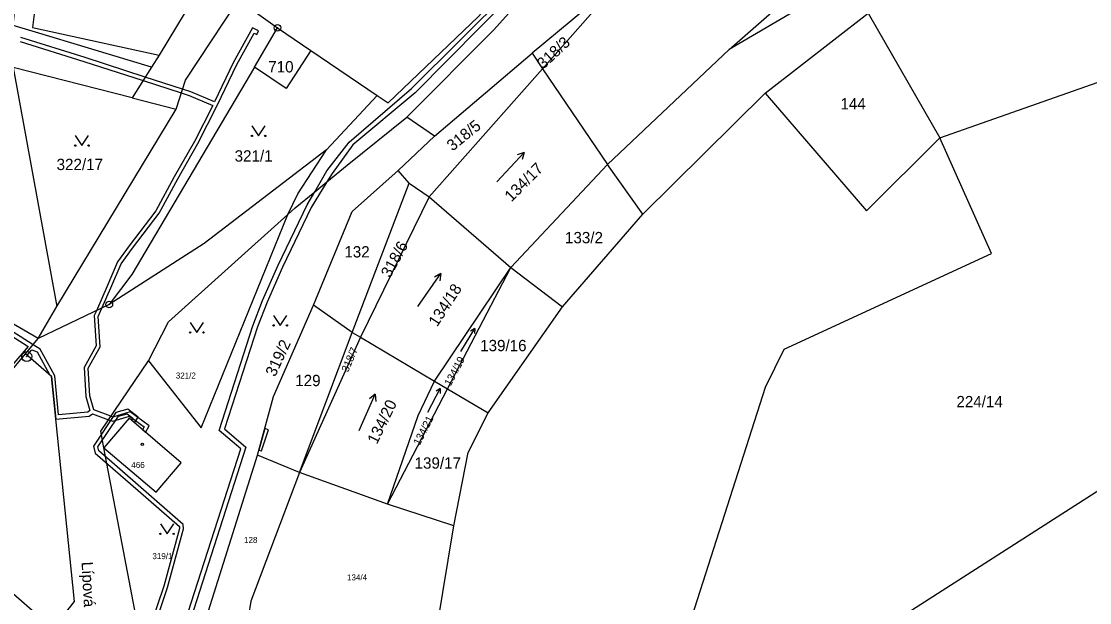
# Model space of a CAD drawing. Extents: x -758582 to -751794, y -998770 to -994350.
# Drawn here: x -755587.2 to -755427.1, y -995334.3 to -995247.1 of the extents above; entities that cross this region are included whole.
import ezdxf

# ---------------------------------------------------------------- set-up
doc = ezdxf.new("R2010")
doc.units = 0
for name, color, linetype in [('Hranice parcel', 7, 'Continuous'), ('Parcelní čísla', 7, 'Continuous'), ('Pop  PČ popisy', 7, 'Continuous'), ('Věcná břemena k části', 7, 'Continuous'), ('Značky bodu BP', 7, 'Continuous'), ('Značky budov', 7, 'Continuous'), ('Značky kultur', 7, 'Continuous')]:
    doc.layers.add(name, color=color, linetype=linetype)

msp = doc.modelspace()

# ---------------------------------------------------------------- linework, layer by layer
at = {"layer": 'Hranice parcel'}
for p, q in [((-755554.28, -995231.7), (-755566.56, -995252.17)), ((-755497.8, -995241.41), (-755509.1, -995254.2)), ((-755475.72, -995257.89), (-755460.26, -995245.87)), ((-755460.26, -995245.87), (-755449.56, -995264.56)), ((-755567.7, -995253.96), (-755585.62, -995248.58)), ((-755552.29, -995253.96), (-755548.82, -995248.07)), ((-755548.82, -995248.07), (-755543.84, -995251.46)), ((-755543.84, -995251.46), (-755533.88, -995258.24)), ((-755525.3, -995264.33), (-755510.67, -995251.89)), ((-755510.67, -995251.89), (-755509.1, -995254.2)), ((-755499.35, -995268.57), (-755481.13, -995251.3)), ((-755566.56, -995252.17), (-755567.7, -995253.96)), ((-755567.7, -995253.96), (-755570.64, -995258.57)), ((-755509.1, -995254.2), (-755526.08, -995273.42)), ((-755509.1, -995254.2), (-755499.35, -995268.57)), ((-755533.88, -995258.24), (-755541.47, -995266.38)), ((-755494.08, -995276.04), (-755475.72, -995257.89)), ((-755570.64, -995258.57), (-755564.04, -995260.28)), ((-755581.92, -995289.89), (-755564.04, -995260.28)), ((-755525.3, -995264.33), (-755529.42, -995261.45)), ((-755530.73, -995269.49), (-755525.3, -995264.33)), ((-755541.42, -995269.53), (-755538.1, -995265.23)), ((-755537.53, -995265.64), (-755540.66, -995269.92)), ((-755543.25, -995272.66), (-755541.42, -995269.53)), ((-755529.08, -995271.36), (-755530.73, -995269.49)), ((-755499.35, -995268.57), (-755513.85, -995284.01)), ((-755494.08, -995276.04), (-755499.35, -995268.57)), ((-755541.43, -995271.17), (-755543.8, -995275.01)), ((-755543.25, -995272.66), (-755541.43, -995271.17)), ((-755540.66, -995269.92), (-755541.43, -995271.17)), ((-755544.39, -995274.61), (-755543.25, -995272.66)), ((-755537.63, -995293.77), (-755529.08, -995271.36)), ((-755529.08, -995271.36), (-755526.08, -995273.42)), ((-755526.08, -995273.42), (-755536.41, -995294.48)), ((-755526.08, -995273.42), (-755513.85, -995284.01)), ((-755506.1, -995289.9), (-755494.08, -995276.04)), ((-755525.31, -995301.08), (-755513.85, -995284.01)), ((-755523.35, -995302.23), (-755513.85, -995284.01)), ((-755513.85, -995284.01), (-755506.1, -995289.9)), ((-755574.05, -995289.57), (-755584.69, -995294.66)), ((-755584.69, -995294.66), (-755581.92, -995289.89)), ((-755537.63, -995293.77), (-755543.42, -995289.65)), ((-755517.23, -995305.83), (-755506.1, -995289.9)), ((-755586.61, -995296.97), (-755584.69, -995294.66)), ((-755545.52, -995314.78), (-755537.63, -995293.77)), ((-755536.41, -995294.48), (-755545.52, -995314.78)), ((-755537.63, -995293.77), (-755536.41, -995294.48)), ((-755536.41, -995294.48), (-755525.31, -995301.08)), ((-755525.31, -995301.08), (-755523.35, -995302.23)), ((-755532.36, -995319.53), (-755523.35, -995302.23)), ((-755523.35, -995302.23), (-755517.23, -995305.83)), ((-755559.19, -995335.53), (-755551.84, -995312.15)), ((-755545.52, -995314.78), (-755551.84, -995312.15)), ((-755532.36, -995319.53), (-755545.52, -995314.78)), ((-755582.49, -995338.18), (-755604.83, -995318.78)), ((-755522.4, -995322.78), (-755532.36, -995319.53)), ((-755525.07, -995339.05), (-755522.4, -995322.78))]:
    msp.add_line(p, q, dxfattribs=at)
for points in [[(-755538.1, -995265.23), (-755528.73, -995257.18), (-755514.16, -995242.6), (-755505.01, -995231.64), (-755487.77, -995216.43), (-755485.53, -995215.06), (-755445.75, -995194.77), (-755445.41, -995195.37), (-755485.15, -995215.66), (-755487.28, -995216.99), (-755504.51, -995232.13), (-755513.52, -995242.92), (-755528.17, -995257.81), (-755537.53, -995265.64)], [(-755529.42, -995261.45), (-755516.42, -995248.35), (-755493.01, -995222.25), (-755447.53, -995198.48)], [(-755481.13, -995251.3), (-755457.2, -995230.32), (-755418.43, -995216.03), (-755380.2, -995211.02), (-755336.91, -995218.43)], [(-755534.63, -995218.44), (-755552.33, -995245.58), (-755548.82, -995248.07)], [(-755386.67, -995226.04), (-755412.78, -995223.97), (-755437.13, -995226.79), (-755445.78, -995230.58), (-755481.13, -995251.3)], [(-755585.62, -995248.58), (-755588.45, -995247.73), (-755586.35, -995227.86)], [(-755564.04, -995260.28), (-755562.65, -995255.93), (-755543.32, -995226.65)], [(-755533.88, -995258.24), (-755532.26, -995259.34), (-755518.72, -995246.36), (-755506.35, -995232.39)], [(-755497.8, -995241.41), (-755502.77, -995245.31), (-755510.67, -995251.89)], [(-755585.26, -995245.62), (-755585.57, -995248), (-755566.56, -995252.17)], [(-755543.84, -995251.46), (-755547.55, -995257.18), (-755552.29, -995253.96)], [(-755570.64, -995258.57), (-755588.47, -995254.04), (-755581.92, -995289.89)], [(-755552.29, -995253.96), (-755570.65, -995285.06), (-755574.05, -995289.57)], [(-755449.56, -995264.56), (-755424.12, -995255.64), (-755410.64, -995253.98)], [(-755475.72, -995257.89), (-755472.3, -995261.82), (-755460.52, -995275.52), (-755449.56, -995264.56)], [(-755541.43, -995271.17), (-755538.37, -995268.67), (-755529.42, -995261.45)], [(-755584.69, -995294.66), (-755603.13, -995283.98), (-755600.61, -995263.4)], [(-755401.75, -995302.11), (-755494.82, -995361.79), (-755475.68, -995301.95), (-755472.86, -995296.26), (-755441.79, -995281.92), (-755449.56, -995264.56)], [(-755541.47, -995266.38), (-755559.84, -995280.42), (-755574.05, -995289.57)], [(-755547.3, -995276.08), (-755545.81, -995272.96), (-755541.47, -995266.38)], [(-755543.42, -995289.65), (-755537.66, -995275.61), (-755530.73, -995269.49)], [(-755547.3, -995276.08), (-755546.19, -995275.06), (-755543.25, -995272.66)], [(-755564.23, -995341.93), (-755554.34, -995311.23), (-755557.56, -995308.48), (-755552.53, -995292.76), (-755551.06, -995288.97), (-755548.71, -995283.66), (-755544.39, -995274.61)], [(-755543.8, -995275.01), (-755548.06, -995283.95), (-755550.36, -995289.2), (-755551.83, -995292.94), (-755556.78, -995308.24), (-755553.56, -995310.96), (-755563.56, -995342.14)], [(-755568.18, -995298.04), (-755560.3, -995308.05), (-755547.3, -995276.08)], [(-755568.18, -995298.04), (-755565.17, -995292.15), (-755547.3, -995276.08)], [(-755551.84, -995312.15), (-755549.43, -995303.35), (-755543.42, -995289.65)], [(-755604.83, -995318.78), (-755602.92, -995316.56), (-755586.61, -995296.97)], [(-755582.49, -995338.18), (-755579.25, -995334.13), (-755582.7, -995300.36), (-755586.61, -995296.97)], [(-755566.67, -995354.01), (-755574.85, -995311.05), (-755575.32, -995308.58), (-755568.18, -995298.04)], [(-755532.36, -995319.53), (-755527.75, -995306.22), (-755525.31, -995301.08)], [(-755522.4, -995322.78), (-755520.25, -995311.79), (-755517.23, -995305.83)], [(-755563.27, -995313.31), (-755571.09, -995306.64), (-755574.85, -995311.05), (-755567.03, -995317.72), (-755563.27, -995313.31)], [(-755545.52, -995314.78), (-755552.84, -995334.08), (-755553.18, -995336.27)]]:
    msp.add_lwpolyline(points, dxfattribs=at)
at = {"layer": 'Věcná břemena k části'}
for points in [[(-755551.93, -995249.05), (-755551.66, -995248.51), (-755552.58, -995248.05), (-755555.49, -995253.3), (-755558.28, -995259.19), (-755561.85, -995257.65), (-755563.07, -995257.26), (-755568.65, -995255.45), (-755577.66, -995252.53), (-755587.33, -995249.51)], [(-755598.06, -995310.72), (-755586.61, -995296.97), (-755586.35, -995297.19), (-755585.64, -995296.39), (-755584.88, -995296.68), (-755583.03, -995300.07), (-755582.7, -995300.36), (-755582.05, -995306.77), (-755577.08, -995306.33), (-755576.55, -995305.95), (-755574.15, -995306.85), (-755573.52, -995307.09), (-755571.01, -995306.33), (-755568.83, -995307.92), (-755569.08, -995308.35), (-755568.62, -995308.75), (-755568.05, -995307.76), (-755570.9, -995305.67), (-755573.5, -995306.45), (-755573.8, -995306.34), (-755576.35, -995305.38), (-755576.98, -995303.25), (-755577.22, -995299.14), (-755575.42, -995295.93), (-755575.71, -995291.35), (-755575.15, -995290.1), (-755573.8, -995287.07), (-755572.28, -995283.49), (-755570.57, -995281.11), (-755566.55, -995275.86), (-755563.8, -995270.71), (-755560.77, -995265.4), (-755557.87, -995259.72), (-755554.95, -995253.58), (-755552.33, -995248.85), (-755551.93, -995249.05)], [(-755587.43, -995250.11), (-755577.85, -995253.1), (-755568.98, -995255.97), (-755563.26, -995257.83), (-755562.06, -995258.22), (-755558.55, -995259.73), (-755561.3, -995265.11), (-755564.33, -995270.42), (-755567.05, -995275.53), (-755571.05, -995280.75), (-755572.8, -995283.19), (-755574.35, -995286.83), (-755575.99, -995290.5), (-755576.32, -995291.24), (-755576.03, -995295.79), (-755577.83, -995299), (-755577.57, -995303.35), (-755576.95, -995305.49), (-755577.29, -995305.74), (-755581.69, -995306.13), (-755582.23, -995300.29), (-755584.41, -995296.29), (-755585.48, -995295.61), (-755592.48, -995291.16)], [(-755643.48, -995337.62), (-755640.25, -995330.48), (-755639.7, -995328.7), (-755632.03, -995328.47), (-755628.34, -995328.42), (-755627.31, -995328.4), (-755621.32, -995321.76), (-755620.58, -995321.49), (-755617.34, -995317.71), (-755616.99, -995316.75), (-755615.43, -995314.83), (-755604.67, -995302.41), (-755603.71, -995289), (-755596.35, -995289.57), (-755592.79, -995291.68), (-755586.22, -995295.85), (-755593.89, -995304.76), (-755600.06, -995312.07), (-755604.15, -995316.69), (-755606.29, -995318.13), (-755608.5, -995320.68), (-755608.78, -995321.82), (-755616.14, -995330.47), (-755621.57, -995336.43)], [(-755569.29, -995343.8), (-755565.32, -995332.01), (-755562.91, -995323.22), (-755562.96, -995322.56), (-755569.31, -995317.02), (-755575.61, -995311.53), (-755575.76, -995310.92), (-755572.67, -995306.31), (-755571.39, -995305.95), (-755570.52, -995306.62), (-755570.73, -995306.92), (-755570.74, -995306.94), (-755570.27, -995307.32), (-755569.7, -995306.49), (-755571.26, -995305.29), (-755573.05, -995305.79), (-755576.41, -995310.8), (-755576.15, -995311.86), (-755569.7, -995317.47), (-755563.54, -995322.85), (-755563.52, -995323.17), (-755565.89, -995331.83), (-755569.86, -995343.61)]]:
    msp.add_lwpolyline(points, dxfattribs=at)
msp.add_lwpolyline([(-755551.64, -995311.41), (-755551.23, -995311.54), (-755550.17, -995308.38), (-755550.75, -995308.18)], close=True, dxfattribs=at)
at = {"layer": 'Značky bodu BP'}
for centre, radius in [((-755548.82, -995248.07), 0.5), ((-755548.82, -995248.07), 0.0303), ((-755574.05, -995289.57), 0.5), ((-755574.05, -995289.57), 0.0303), ((-755586.43, -995297.38), 0.75), ((-755586.43, -995297.38), 0.03)]:
    msp.add_circle(centre, radius, dxfattribs=at)
at = {"layer": 'Značky budov'}
msp.add_circle((-755569.1, -995310.55), 0.175, dxfattribs=at)
at = {"layer": 'Značky kultur'}
for p, q in [((-755515.96, -995271.15), (-755511.87, -995266.76)), ((-755511.87, -995266.76), (-755512.9, -995267.13)), ((-755511.87, -995266.76), (-755512.17, -995267.82)), ((-755527.77, -995289.86), (-755524.33, -995284.94)), ((-755524.33, -995284.94), (-755525.3, -995285.46)), ((-755524.33, -995284.94), (-755524.48, -995286.03)), ((-755521.37, -995296.6), (-755519.24, -995293.19)), ((-755519.24, -995293.19), (-755519.88, -995293.57)), ((-755519.24, -995293.19), (-755519.31, -995293.92)), ((-755536.6, -995308.49), (-755534.17, -995303.01)), ((-755534.17, -995303.01), (-755535.02, -995303.7)), ((-755534.17, -995303.01), (-755534.1, -995304.1)), ((-755526.32, -995305.72), (-755524.44, -995302.17)), ((-755524.44, -995302.17), (-755525.04, -995302.59)), ((-755524.44, -995302.17), (-755524.45, -995302.9))]:
    msp.add_line(p, q, dxfattribs=at)
for points in [[(-755552.67, -995262.79), (-755551.67, -995264.29), (-755550.67, -995262.79)], [(-755579.16, -995264.24), (-755578.16, -995265.74), (-755577.16, -995264.24)], [(-755549.42, -995291.21), (-755548.42, -995292.71), (-755547.42, -995291.21)], [(-755561.93, -995292.25), (-755560.93, -995293.75), (-755559.93, -995292.25)], [(-755566.39, -995322.47), (-755565.39, -995323.97), (-755564.39, -995322.47)]]:
    msp.add_lwpolyline(points, dxfattribs=at)
for centre in [(-755552.67, -995264.29), (-755550.67, -995264.29), (-755579.16, -995265.74), (-755577.16, -995265.74), (-755561.93, -995293.75), (-755559.93, -995293.75), (-755549.42, -995292.71), (-755547.42, -995292.71), (-755566.39, -995323.97), (-755564.39, -995323.97)]:
    msp.add_circle(centre, 0.1, dxfattribs=at)

# ---------------------------------------------------------------- texts
at = {"layer": 'Parcelní čísla'}
for s, height, rotation, p in [('318/3', 1.7, 43, (-755508.97, -995254.35)), ('318/5', 1.7, 39, (-755522.6, -995266.65)), ('134/17', 1.7, 45, (-755513.77, -995274.27)), ('318/6', 1.7, 61, (-755531.96, -995285.67)), ('134/18', 1.7, 57, (-755524.9, -995293.01)), ('319/2', 1.7, 65, (-755549.19, -995300.52)), ('318/7', 1.14, 67, (-755538.25, -995299.81)), ('134/19', 1.14, 62, (-755522.88, -995301.89)), ('134/20', 1.7, 64, (-755533.93, -995310.64)), ('134/21', 1.14, 63, (-755527.52, -995310.79))]:
    msp.add_text(s, height=height, rotation=rotation, dxfattribs=at).set_placement(p)
for s, height, p in [('710', 1.7, (-755550.22, -995254.76)), ('144', 1.7, (-755464.44, -995260.32)), ('321/1', 1.7, (-755555.26, -995268.14)), ('322/17', 1.7, (-755581.95, -995269.41)), ('133/2', 1.7, (-755505.73, -995280.39)), ('132', 1.7, (-755538.81, -995282.52)), ('139/16', 1.7, (-755518.45, -995296.58)), ('321/2', 0.9, (-755564.08, -995300.68)), ('129', 1.7, (-755546.17, -995301.82)), ('224/14', 1.7, (-755447.05, -995304.99)), ('139/17', 1.7, (-755528.28, -995314.2)), ('466', 0.9, (-755570.75, -995314.09)), ('128', 0.9, (-755553.85, -995325.34)), ('319/1', 0.9, (-755567.59, -995327.77)), ('134/4', 0.9, (-755538.41, -995330.96))]:
    msp.add_text(s, height=height, dxfattribs=at).set_placement(p)
at = {"layer": 'Pop  PČ popisy'}
msp.add_text('Lípová', height=1.7, rotation=273, dxfattribs=at).set_placement((-755578.21, -995328.2))

doc.saveas('drawing.dxf')
